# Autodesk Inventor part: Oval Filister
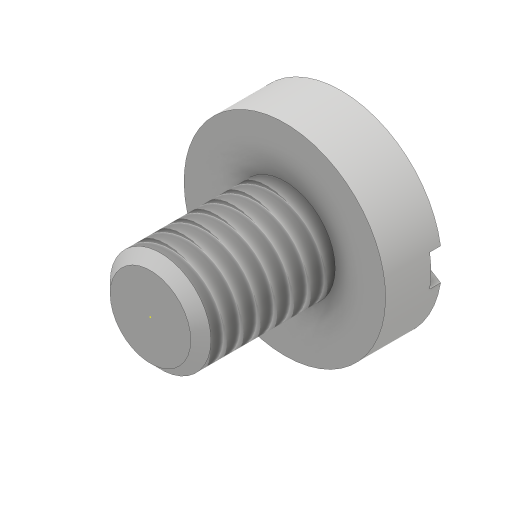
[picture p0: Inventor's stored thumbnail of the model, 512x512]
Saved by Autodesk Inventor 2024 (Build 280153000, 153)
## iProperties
Created: 2016-06
Part Number: Oval Filister
Material: Generic
Document SubType Name: Modeling
Designer: CADCIM
Density: 1 g/cm^3
Appearance: Default
Mass: 0.639925 g
Surface Area: 5.32794 cm^2
Volume: 0.639925 cm^3
Author: CADCIM
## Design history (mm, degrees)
sketch "Sketch2"
  geometry: C1 r 3 at (0, 0); 1 further point
  constraints: 1 centre point, 1 coincident
  dimensions: "d0" = 6 diameter of C1
extrude "Extrusion1" new body sketch "Sketch2" distance "d1" = 8; taper "d2" = 0 deg
revolve "Revolution1" stored, may be unused: angle "d6" = 90 deg
workplane "Work Plane1"
sketch "Sketch5"
  geometry: L1 (6.611, -0.95)-(-6.611, -0.95); L2 (-6.611, -0.95)-(-6.611, 0.95); L3 (-6.611, 0.95)-(6.611, 0.95); L4 (6.611, 0.95)-(6.611, -0.95); L5 (6.611, 0)-(-6.611, 0); 2 further points
  constraints: 10 end point, 3 midpoint, 2 parallel, 1 coincident, 1 horizontal, 1 perpendicular
  dimensions: "d8" = 1.9 distance of L3.end L1.start
extrude "Extrusion2" cut sketch "Sketch5" distance "d9" = 1.9; taper "d10" = 0 deg
thread "Thread1" dims "d11" = 10, "d12" = 0
chamfer "Chamfer1" distance "d13" = 0.6; stored, may be unused: second distance "d14" = 2, angle "d15" = 45 deg
body "Solid1"
sketch "Sketch1"
  geometry: 1 further point
sketch "Sketch3"
  geometry: 1 further point
sketch "Sketch4"
  geometry: L1 (8, 0)-(8, -6); L2 (8, -3)-(8, 3) reference; L3 (8, -6)-(11.35, -6); L4 (12.6, 0)-(8, 0); A1 r 15.025 centre (-2.425, 0) between (11.35, -6) and (12.6, 0); 2 further points
  constraints: 6 end point, 2 midpoint, 2 point on circle, 1 centre point, 1 horizontal, 1 horizontal alignment, 1 perpendicular, 1 point on line, 1 vertical
  dimensions: "d3" = 6 distance of L1.start L1.end; "d4" = 4.6 distance of L4.start L1.start; "d5" = 1.25 horizontal distance of L3.end L4.start
other parameters: "d7" = -4.6
